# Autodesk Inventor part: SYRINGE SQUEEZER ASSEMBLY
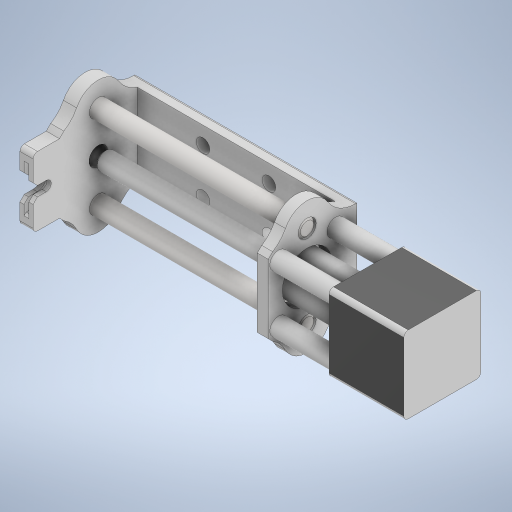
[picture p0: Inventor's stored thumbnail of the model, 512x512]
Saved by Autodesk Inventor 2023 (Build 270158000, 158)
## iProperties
Created: 2025-07
Part Number: SYRINGE SQUEEZER ASSEMBLY
Material: Generic
Document SubType Name: Modeling
Designer: erjon
Density: 1 g/cm^3
Appearance: Default
Author: erjon
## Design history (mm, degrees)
feature "Base1"
feature "Base2"
feature "Base3"
feature "Base4"
feature "Base5"
feature "Base6"
body "Solid1"
body "Solid2"
body "Solid3"
body "Solid4"
body "Solid5"
body "Solid6"
